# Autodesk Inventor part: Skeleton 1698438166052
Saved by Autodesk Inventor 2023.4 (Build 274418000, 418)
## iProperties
Created: 2023-10
Part Number: Skeleton 1698438166052
Material: 10GA CRS
Document SubType Name: Sheet Metal
Designer: Fred L.
Density: 7.86 g/cm^3
Sheet Metal Rule: 10 ga
Appearance: Metal-Steel
Quantity: 0
Mass: 0
SurfaceArea: 0
_SkeletonDoc: Frame Skeleton File
_Version: 15.0.0
Author: Fred L.
Revision Number: 00
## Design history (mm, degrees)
sketch "Reference Skeleton"
body "Solid1"
other parameters: "Thickness" = 3.429 (derived), "KFactor" = 4.4, "BendRadius" = 3.429 (= Thickness), "BendReliefWidth" = 1.7145 (= 0.5 x Thickness), "BendReliefDepth" = 1.7145 (= 0.5 x Thickness), "CornerReliefSize" = 13.716 (= 4 x Thickness), "SeamGap" = 0.00508, "MinimumRemnant" = 6.858 (= 2 x Thickness), "TransitionRadius" = 3.429 (= BendRadius), "JacobiRadiusSize" = 3.429 (= BendRadius), "GapSize" = 0.254 (derived), "alga10" = 2.5908 [user parameter], "alga11" = 2.3114 [user parameter], "alga12" = 2.0574 [user parameter], "alga14" = 1.6256 [user parameter], "alga16" = 1.2954 [user parameter], "alga18" = 1.016 [user parameter], "alga20" = 0.8128 [user parameter], "alga22" = 0.635 [user parameter], "alga24" = 0.508 [user parameter], "ga9" = 3.6576 [user parameter], "ga10" = 3.4036 [user parameter], "ga11" = 3.0226 [user parameter], "ga12" = 2.65684 [user parameter], "ga14" = 1.89738 [user parameter], "ga16" = 1.51892 [user parameter], "ga18" = 1.21412 [user parameter], "ga20" = 0.91186 [user parameter], "ga22" = 0.75946 [user parameter], "ga24" = 0.60706 [user parameter], "gvga12" = 2.75336 [user parameter], "gvga14" = 1.9939 [user parameter], "gvga16" = 1.6129 [user parameter], "gvga18" = 1.31064 [user parameter], "gvga20" = 1.00584 [user parameter], "gvga22" = 0.85344 [user parameter], "gvga24" = 0.70104 [user parameter], "ssga10" = 3.57124 [user parameter], "ssga11" = 3.175 [user parameter], "ssga12" = 2.7686 [user parameter], "ssga14" = 1.98374 [user parameter], "ssga16" = 1.5875 [user parameter], "ssga18" = 1.27 [user parameter], "ssga20" = 0.9398 [user parameter], "ssga22" = 0.7874 [user parameter], "ssga24" = 0.635 [user parameter], "Length" = 0 [user parameter; used in 1 equation term], "Width" = 0 [user parameter; used in 1 equation term], "Area" = 0 (computed from Length, Width) [user parameter]
